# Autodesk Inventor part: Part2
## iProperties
Created: 2002-02
Part Number: Part2
Document SubType Name: ﾓﾃﾞﾘﾝｸﾞ
Designer: Administrator
Control State: 0
Master: False
Checked Out: False
Shininess: 64.0
Length Units: 11269
Angle Units: 11279
Time Units: 11290
Mass Units: 11284
Length Display Precision: 2
Angle Display Precision: 1
Density: 0.0
Volumn: 0.0
Area: 0.0
PropertySet Name: Model Information
Author: Administrator
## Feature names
1. 押し出し1 [Extrusion]
2. 押し出し2 [Extrusion]
3. 押し出し3 [Extrusion]
4. 押し出し4 [Extrusion]
